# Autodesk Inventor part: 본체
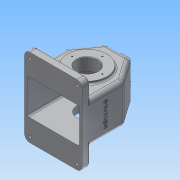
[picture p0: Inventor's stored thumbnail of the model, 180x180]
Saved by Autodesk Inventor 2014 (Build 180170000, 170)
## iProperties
Created: 2016-12
Part Number: 본체
Material: Aluminum 6061
Document SubType Name: Modeling
Designer: user
Mass: 1067.29 g
Surface Area: 1138.05 cm^2
Volume: 393.834 cm^3
Density: 2.71 g/cm^3
Appearance: Aluminum - Flat
Author: user
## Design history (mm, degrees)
sketch "Sketch1"
  geometry: L1 (-55, 0)-(-23.491, 45); L2 (-23.491, 45)-(0, 45); L3 (0, 45)-(0, -80); L4 (0, -80)-(-55, -80); L5 (-55, -80)-(-55, 0); L6 (-77, 0)-(77, 0) reference; L7 (55, 0)-(23.491, 45); L8 (0, -80)-(55, -80); L9 (55, -80)-(55, 0); L10 (23.491, 45)-(0, 45); 1 further point
  constraints: 18 end point, 3 symmetric about line, 2 horizontal, 2 point on line, 1 parallel, 1 perpendicular
  dimensions: "d0" = 55 deg angle of L6 L1; "d1" = 80 distance between parallel lines of L6 L4; "d2" = 125 distance between parallel lines of L2 L4; "d3" = 55 distance between parallel lines of L3 L5
extrude "Extrusion1" new body sketch "Sketch1" stored distance "d4" = 77; taper "d5" = 0 deg
shell "Shell1" dims "d32" = 5
sketch "Sketch2"
  geometry: L1 (0, -113.5)-(110, -113.5); L2 (110, -113.5)-(110, 36.5); L3 (110, 36.5)-(0, 36.5); L4 (0, 36.5)-(0, -113.5); L5 (0, -113.5)-(110, 36.5); L6 (110, -113.5)-(0, 36.5); 1 further point
  constraints: 12 end point, 2 midpoint, 2 parallel, 1 horizontal, 1 perpendicular
  dimensions: "d6" = 110 distance between parallel lines of L2 L4; "d7" = 150 distance of L1.end L2.end
extrude "Extrusion2" join sketch "Sketch2" distance "d8" = 15; taper "d9" = 0 deg
workplane "Work Plane1"
sketch "Sketch3"
  geometry: L1 (23.491, 45)-(-23.491, 45) reference; L2 (-12.5, 45)-(12.5, 45); L3 (12.5, 45)-(12.5, 60); L4 (12.5, 60)-(-12.5, 60); L5 (-12.5, 60)-(-12.5, 45); L6 (55, -80)-(-55, -80) reference; L7 (-7.5, 45)-(7.5, 45); L8 (7.5, 45)-(7.5, 55); L9 (7.5, 55)-(-7.5, 55); L10 (-7.5, 55)-(-7.5, 45); 3 further points
  constraints: 16 end point, 4 parallel, 2 horizontal, 2 midpoint, 2 perpendicular, 2 point on line, 2 vertical alignment
  dimensions: "d11" = 25 distance of L3.end L4.end; "d12" = 140 distance between parallel lines of L6 L4; "d13" = 15 distance of L8.end L9.end; "d14" = 5 distance between parallel lines of L9 L4
extrude "Extrusion3" join sketch "Sketch3" stored distance "d15" = 8; taper "d16" = 0 deg
mirror "Mirror1"
fillet "Fillet1" dims "d17" = 8
fillet "Fillet2" dims "d18" = 3
fillet "Fillet3" dims "d19" = 3
fillet "Fillet4" dims "d20" = 1
fillet "Fillet6" dims "d22" = 1
fillet "Fillet7" dims "d23" = 1
fillet "Fillet8" dims "d24" = 1
sketch "Sketch4"
  geometry: L1 (55, -80)-(-55, -80) reference; C1 r 31 at (0, -15); 1 further point
  constraints: 1 centre point
  dimensions: "d25" = 62 diameter of C1; "d26" = 65 distance from line of L1 C1.centre
extrude "Extrusion4" join sketch "Sketch4" distance "d27" = 10; taper "d28" = 0 deg
sketch "Sketch5"
  geometry: C1 r 31 at (0, -15) reference; C2 r 37.5 at (0, -15); 1 further point
  constraints: 1 centre point, 1 coincident
  dimensions: "d29" = 75 diameter of C2
extrude "Extrusion5" join sketch "Sketch5" distance "d30" = 5; taper "d31" = 0 deg
sketch "Sketch6"
  geometry: L1 (5, -108.5)-(105, -108.5); L2 (105, -108.5)-(105, -41.5); L3 (105, -41.5)-(5, -41.5); L4 (5, -41.5)-(5, -108.5); L5 (5, -108.5)-(105, -41.5); L6 (105, -108.5)-(5, -41.5); 1 further point
  constraints: 12 end point, 2 midpoint, 2 parallel, 1 horizontal, 1 perpendicular
extrude "Extrusion6" cut sketch "Sketch6" distance "d33" = 15; taper "d34" = 0 deg
fillet "Fillet9" dims "d35" = 10
fillet "Fillet10" dims "d36" = 10
fillet "Fillet11" dims "d37" = 8
fillet "Fillet12" dims "d38" = 3
fillet "Fillet13" dims "d39" = 3
fillet "Fillet14" dims "d40" = 3
fillet "Fillet15" dims "d41" = 5
sketch "Sketch7"
  geometry: L1 (36.147, 33.5)-(-2.522, 33.5) reference; L2 (26, 33.5)-(12, 19.5); L3 (22.5, 43.5)-(-52.5, 43.5) reference; L4 (-15, 33.5)-(-15, 19.5); L5 (12, 19.5)-(-15, 19.5); L6 (26, 33.5)-(-15, 33.5); L7 (-2.522, 33.5)-(-80, 33.5) reference; 1 further point
  constraints: 8 end point, 2 perpendicular, 2 point on line
  dimensions: "d42" = 24 distance between parallel lines of L3 L5; "d43" = 135 deg angle of L5 L2; "d44" = 54 diameter of L2.end L4
revolve "Revolution1" sketch "Sketch7" stored, may be unused: angle "d45" = 90 deg
fillet "Fillet16" dims "d46" = 3
fillet "Fillet17" dims "d47" = 3
sketch "Sketch8"
  geometry: C1 r 37.5 at (0, 0) reference; C2 r 20 at (0, 0); 1 further point
  constraints: 1 centre point, 1 coincident
  dimensions: "d48" = 40 diameter of C2
extrude "Extrusion7" cut sketch "Sketch8" stored distance "d49" = 15; taper "d50" = 0 deg
chamfer "Chamfer1" distance "d51" = 1; stored, may be unused: second distance "d52" = 2, angle "d53" = 45 deg
sketch "Sketch9" dims "d54" = 58
  geometry: C1 r 21 at (0, 0) reference; 3 further points
  constraints: 1 coincident, 1 vertical alignment, 2 other
hole "Hole1" sketch "Sketch9" at (0, 29) diameter "d55" = 2.459; stored, may be unused: countersink angle "d59" = 90 deg, drill point angle "d61" = 118 deg; dims "d56" = 6, "d57" = 4, "d58" = 2, "d60" = 8
pattern_circular "Circular Pattern1" dims angle "d63" = 360 deg
sketch "Sketch10" dims "d65" = 52
  geometry: C1 r 21 at (0, 0) reference; 3 further points
  constraints: 1 coincident, 1 vertical alignment, 2 other
hole "Hole2" sketch "Sketch10" at (0, 26) diameter "d66" = 2.459; stored, may be unused: countersink angle "d70" = 90 deg, drill point angle "d72" = 118 deg; dims "d67" = 6, "d68" = 4, "d69" = 2, "d71" = 8
pattern_circular "Circular Pattern2" dims angle "d74" = 360 deg
sketch "Sketch11"
  geometry: L1 (102, 72)-(8, 72) reference; L2 (5, 69)-(5, 8) reference; L3 (8, 5)-(102, 5) reference; L4 (105, 8)-(105, 69) reference; L5 (102, -3)-(8, -3) reference; L6 (0, 8)-(0, 69) reference; L7 (8, 80)-(102, 80) reference; L8 (110, 69)-(110, 8) reference; L9 (107, -26.5)-(107, -1.798) reference; L10 (10, -33.5)-(100, -33.5) reference; L11 (3, -1.798)-(3, -26.5) reference; L12 (3, 103.5)-(3, 78.798) reference; L13 (100, 110.5)-(10, 110.5) reference; L14 (107, 78.798)-(107, 103.5) reference; A1 r 7 centre (100, 103.5) between (107, 103.5) and (100, 110.5) reference; A2 r 7 centre (10, 103.5) between (10, 110.5) and (3, 103.5) reference; A3 r 3 centre (102, 69) between (105, 69) and (102, 72) reference; A4 r 3 centre (8, 69) between (8, 72) and (5, 69) reference; A5 r 3 centre (8, 8) between (5, 8) and (8, 5) reference; A6 r 3 centre (102, 8) between (102, 5) and (105, 8) reference; A7 r 11 centre (102, 8) between (102, -3) and (107, -1.798) reference; A8 r 11 centre (8, 8) between (3, -1.798) and (8, -3) reference; A9 r 8 centre (8, 8) between (0, 8) and (0.585, 4.998) reference; A10 r 8 centre (8, 69) between (0.585, 72.002) and (0, 69) reference; A11 r 11 centre (8, 69) between (8, 80) and (3, 78.798) reference; A12 r 11 centre (102, 69) between (107, 78.798) and (102, 80) reference; A13 r 8 centre (102, 69) between (110, 69) and (109.415, 72.002) reference; A14 r 8 centre (102, 8) between (109.415, 4.998) and (110, 8) reference; A15 r 7 centre (100, -26.5) between (100, -33.5) and (107, -26.5) reference; A16 r 7 centre (10, -26.5) between (3, -26.5) and (10, -33.5) reference; A17 r 7 centre (10, 103.5) between (10, 110.5) and (3, 103.5) reference; A18 r 7 centre (100, 103.5) between (107, 103.5) and (100, 110.5) reference; 1 further point
  constraints: 4 other
hole "Hole3" sketch "Sketch11" at (10, 103.5), (100, 103.5), (100, -26.5), (10, -26.5) diameter "d76" = 5; stored, may be unused: countersink angle "d80" = 90 deg, drill point angle "d82" = 118 deg; dims "d77" = 6, "d78" = 12, "d79" = 5, "d81" = 8
sketch "Sketch12"
  geometry: L1 (0, 0)-(130, 0) reference; L2 (26.5, 76.847)-(26.5, 18) reference; 2 further points
  constraints: 1 other
  dimensions: "d83" = 38.5 distance from line of point (65, 45) L2; "d84" = 45 distance from line of L1 point (65, 45)
emboss "Emboss1" sketch "Sketch12" dims "d0" = 55 deg, "d1" = 80, "d2" = 125, "d3" = 55, "d85" = 0.5, "d86" = 0
body "Solid1"
node "Project Cut Edges1"
other parameters: "d10" = 18
